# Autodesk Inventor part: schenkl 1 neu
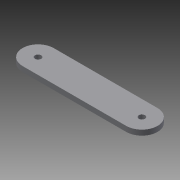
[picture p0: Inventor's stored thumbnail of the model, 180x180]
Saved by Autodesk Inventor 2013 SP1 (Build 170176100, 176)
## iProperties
Created: 2012-11
Part Number: schenkl 1 neu
Material: Allgemein
Document SubType Name: Modeling
Designer: macuser
Density: 1 g/cm^3
Author: macuser
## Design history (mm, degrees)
sketch "Skizze1"
  geometry: L1 (0, -42)-(0, 42) reference; L2 (-82, 0)-(282, 0) reference; L3 (0, 30)-(200, 30); L4 (0, -30)-(200, -30); C1 r 6 at (0, 0); C2 r 6 at (200, 0); A1 r 30 centre (0, 0) between (0, 30) and (0, -30); A2 r 30 centre (200, 0) between (200, 30) and (200, -30); 1 further point
  constraints: 4 centre point, 4 end point, 4 point on circle, 2 coincident, 2 parallel, 2 point on line, 2 tangent
  dimensions: "d0" = 60 diameter of A1; "d1" = 60 diameter of A2; "d2" = 0 distance from line of L1 A1.centre; "d3" = 200 distance of A2.centre point (0, 0); "d4" = 12 diameter of C1; "d5" = 12 diameter of C2
extrude "Extrusion1" new body sketch "Skizze1" distance "d6" = 10; taper "d7" = 0 deg
node "Volumenkörper1"
